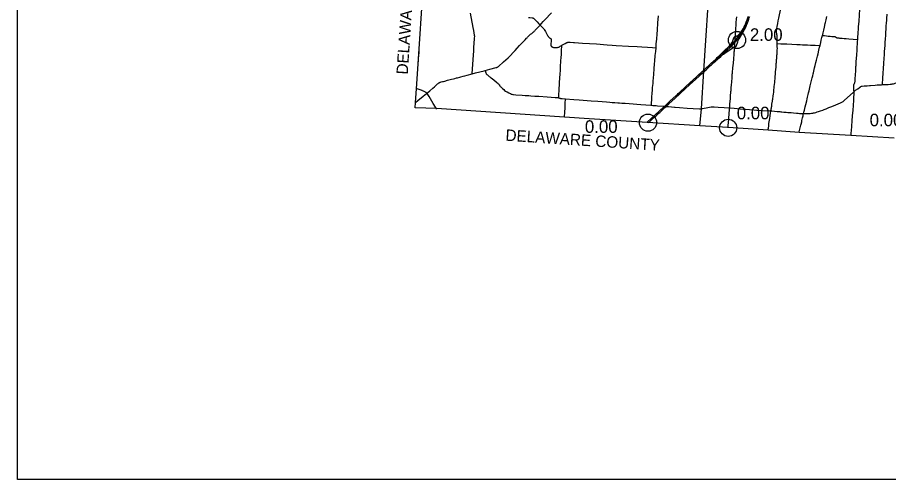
# Model space of a CAD drawing. Extents: x 1813937 to 1948437, y 826606 to 1022856.
# Drawn here: x 1813937 to 1890191, y 826606 to 867056 of the extents above; entities that cross this region are included whole.
import ezdxf

# ---------------------------------------------------------------- set-up
doc = ezdxf.new("R2010")
doc.units = 0
for name, color, linetype in [('Default', 7, 'Continuous'), ('GM_X_Adjacent_County_Text', 7, 'Continuous'), ('GM_X_County', 7, 'Continuous'), ('GM_X_County_Road', 7, 'Continuous'), ('GM_X_Interchange_Ramps', 7, 'Continuous'), ('GM_X_Interstate_Route', 7, 'Continuous'), ('GM_X_State_Route', 7, 'Continuous'), ('GM_X_Township', 7, 'Continuous'), ('GM_X_Township_Road', 7, 'Continuous'), ('SC_Scratch1', 7, 'Continuous')]:
    doc.layers.add(name, color=color, linetype=linetype)

msp = doc.modelspace()

# ---------------------------------------------------------------- linework, layer by layer
at = {"layer": 'Default'}
for centre in [(1876923, 865078), (1869130, 857850), (1876155, 857392)]:
    msp.add_circle(centre, 750, dxfattribs=at)
at = {"layer": 'GM_X_County'}
msp.add_lwpolyline([(1890695, 856480), (1886895, 856734), (1882352, 856998), (1879641, 857188), (1876143, 857428), (1873671, 857558), (1869100, 857855), (1863977, 858188), (1861827, 858324), (1850615, 859080), (1848752, 859146), (1848787, 859601), (1848864, 860810), (1849106, 864311), (1849634, 872258)], dxfattribs=at)
at = {"layer": 'GM_X_County_Road'}
for points in [[(1880446, 864770), (1880445, 864839), (1880441, 865118), (1880441, 865256), (1880436, 865364), (1880425, 865461), (1880415, 865553), (1880404, 865637), (1880388, 865760), (1880378, 865837), (1880375, 865898), (1880378, 865959), (1880388, 866024), (1880401, 866097), (1880436, 866266), (1880487, 866526), (1880531, 866751), (1880580, 866992), (1880753, 867844)], [(1853748, 862117), (1853750, 862165), (1853770, 862493), (1853801, 862984), (1853822, 863312), (1853856, 863803), (1853874, 864081), (1853894, 864409), (1853921, 864802), (1853950, 865195), (1853955, 865274), (1853961, 865391), (1853961, 865426), (1853960, 865457), (1853958, 865482), (1853954, 865506), (1853881, 865910), (1853831, 866184), (1853607, 867428)], [(1859687, 866387), (1859824, 866534), (1859968, 866692), (1860116, 866845), (1860675, 867445)], [(1869835, 864397), (1869843, 864490), (1869862, 864735), (1869893, 865144), (1869930, 865619), (1869952, 865930), (1870002, 866568), (1870050, 867206)], [(1884401, 865479), (1884424, 865573), (1884458, 865716), (1884513, 865939), (1884579, 866210), (1884651, 866513), (1884679, 866621), (1884706, 866733), (1884733, 866844), (1884766, 866988), (1884800, 867132)], [(1887494, 865122), (1887497, 865170), (1887500, 865235), (1887511, 865399), (1887526, 865595), (1887533, 865708), (1887559, 866050), (1887573, 866263), (1887603, 866704), (1887641, 867277), (1887670, 867741)], [(1854870, 862411), (1855302, 862523), (1855842, 862663), (1855880, 862674), (1855903, 862682), (1855921, 862689), (1855948, 862702), (1855990, 862727), (1856042, 862766), (1856484, 863158), (1856890, 863515), (1856986, 863605), (1857032, 863653), (1857075, 863700), (1857361, 864017), (1857505, 864175), (1857669, 864358), (1857895, 864595), (1858054, 864761), (1858190, 864904), (1858262, 864979), (1858381, 865102), (1858508, 865235), (1858543, 865271), (1858599, 865329), (1858715, 865445), (1858861, 865577), (1858960, 865663), (1859073, 865757), (1859126, 865803), (1859182, 865855), (1859217, 865889), (1859254, 865927), (1859342, 866020), (1859567, 866259), (1859687, 866387)], [(1859687, 866387), (1859699, 866375), (1859714, 866360), (1859801, 866272), (1859881, 866197), (1859909, 866170), (1859925, 866154), (1859941, 866138), (1859949, 866128), (1859963, 866112), (1859984, 866085), (1860010, 866049), (1860049, 865995), (1860149, 865825), (1860221, 865697), (1860311, 865522), (1860337, 865477), (1860361, 865438), (1860380, 865408), (1860397, 865384), (1860414, 865363), (1860432, 865343), (1860449, 865327), (1860477, 865302), (1860502, 865281), (1860538, 865255), (1860568, 865234), (1860596, 865215), (1860609, 865206), (1860618, 865199), (1860621, 865197), (1860624, 865194), (1860626, 865192), (1860629, 865189), (1860635, 865184), (1860643, 865175), (1860645, 865172), (1860648, 865168), (1860650, 865165), (1860652, 865162), (1860654, 865157), (1860655, 865154), (1860655, 865151), (1860656, 865149), (1860656, 865146), (1860656, 865113), (1860655, 865093), (1860652, 865044), (1860644, 864918), (1860636, 864801), (1860631, 864730), (1860628, 864661), (1860628, 864646), (1860628, 864634), (1860629, 864625), (1860630, 864613), (1860632, 864604), (1860634, 864595), (1860639, 864580), (1860643, 864573), (1860649, 864562), (1860656, 864553), (1860665, 864539), (1860676, 864528), (1860687, 864516), (1860699, 864504), (1860711, 864494), (1860718, 864488), (1860726, 864482), (1860736, 864475), (1860748, 864468), (1860761, 864462), (1860772, 864457), (1860784, 864451), (1860794, 864447), (1860805, 864443), (1860816, 864440), (1860856, 864428), (1860878, 864423), (1860920, 864417), (1860985, 864412), (1861066, 864413), (1861147, 864419), (1861212, 864429), (1861260, 864440), (1861322, 864462), (1861381, 864489), (1861452, 864528), (1861493, 864555), (1861570, 864613), (1861586, 864625), (1861605, 864638)], [(1861605, 864638), (1861697, 864680), (1861770, 864715), (1861870, 864769), (1862028, 864852), (1862073, 864871), (1862095, 864878), (1862120, 864885), (1862130, 864888), (1862150, 864891), (1862162, 864892), (1862171, 864892), (1862183, 864892), (1862201, 864892), (1862224, 864891), (1862257, 864889), (1862318, 864885), (1862619, 864866), (1862686, 864861), (1863397, 864814), (1864619, 864733), (1864959, 864711), (1865239, 864692), (1865546, 864671), (1866005, 864637), (1866352, 864612), (1867418, 864549), (1868175, 864502), (1868595, 864476), (1869081, 864445), (1869537, 864416), (1869835, 864397)], [(1880367, 863051), (1880377, 863199), (1880383, 863268), (1880391, 863382), (1880397, 863469), (1880406, 863567), (1880414, 863666), (1880419, 863752), (1880426, 863840), (1880432, 863919), (1880440, 864028), (1880446, 864115), (1880453, 864206), (1880455, 864322), (1880453, 864484), (1880446, 864770)], [(1884190, 864602), (1884252, 864855), (1884305, 865078), (1884359, 865302), (1884382, 865397), (1884401, 865479)], [(1887166, 860572), (1887164, 860625), (1887155, 860789), (1887150, 860871), (1887144, 860969), (1887141, 861068), (1887142, 861101), (1887145, 861134), (1887149, 861150), (1887153, 861166), (1887159, 861182), (1887173, 861212), (1887206, 861269), (1887221, 861298), (1887233, 861328), (1887242, 861359), (1887248, 861390), (1887254, 861455), (1887262, 861586), (1887268, 861701), (1887286, 861995), (1887312, 862404), (1887327, 862634), (1887335, 862748), (1887342, 862862), (1887349, 862961), (1887366, 863206), (1887382, 863451), (1887404, 863779), (1887432, 864188), (1887452, 864482), (1887469, 864728), (1887483, 864957), (1887494, 865122)], [(1861321, 860011), (1861325, 860133), (1861334, 860346), (1861349, 860624), (1861394, 861360), (1861419, 861736), (1861443, 862112), (1861461, 862407), (1861483, 862734), (1861517, 863257), (1861535, 863535), (1861551, 863797), (1861571, 864108), (1861605, 864638)], [(1869425, 859366), (1869437, 859552), (1869463, 859879), (1869479, 860092), (1869503, 860386), (1869527, 860714), (1869541, 860910), (1869571, 861286), (1869588, 861515), (1869606, 861727), (1869637, 862103), (1869675, 862561), (1869711, 862986), (1869732, 863231), (1869775, 863722), (1869807, 864081), (1869835, 864397)], [(1882749, 858641), (1882781, 858766), (1882823, 858927), (1882904, 859244), (1882948, 859428), (1883026, 859753), (1883068, 859929), (1883106, 860089), (1883158, 860312), (1883190, 860461), (1883229, 860629), (1883269, 860791), (1883333, 861063), (1883508, 861779), (1883548, 861938), (1883592, 862113), (1883612, 862192), (1883721, 862655), (1883766, 862846), (1883830, 863118), (1883877, 863309), (1883965, 863676), (1884016, 863883), (1884089, 864186), (1884150, 864441), (1884190, 864602)], [(1879893, 858874), (1879899, 858914), (1879910, 858992), (1879918, 859061), (1879931, 859139), (1879943, 859213), (1879959, 859293), (1879975, 859388), (1879986, 859464), (1880023, 859712), (1880035, 859806), (1880053, 859910), (1880067, 859997), (1880081, 860098), (1880092, 860193), (1880111, 860342), (1880134, 860505), (1880161, 860729), (1880175, 860889), (1880189, 861041), (1880201, 861164), (1880228, 861384), (1880242, 861531), (1880253, 861663), (1880270, 861893), (1880286, 862093), (1880305, 862302), (1880320, 862485), (1880339, 862702), (1880350, 862834), (1880360, 862959), (1880366, 863040), (1880367, 863051)], [(1849777, 860431), (1849850, 860491), (1850041, 860645), (1850308, 860862), (1850446, 860977), (1850478, 861005), (1850507, 861033), (1850563, 861092), (1850653, 861188), (1850701, 861232), (1850764, 861283), (1850793, 861303), (1850831, 861328), (1850859, 861344), (1850888, 861360), (1850911, 861370), (1850947, 861385), (1850983, 861397), (1851025, 861410), (1851135, 861438), (1851230, 861461), (1851339, 861488), (1851596, 861554), (1851929, 861642), (1852119, 861692), (1852230, 861721), (1852373, 861757), (1852468, 861781), (1852658, 861831), (1852753, 861857), (1852943, 861907), (1853101, 861949), (1853307, 862004), (1853748, 862117)], [(1853748, 862117), (1854032, 862192), (1854794, 862391), (1854870, 862411)], [(1854870, 862411), (1854930, 862215), (1854953, 862153), (1854969, 862124), (1854990, 862097), (1855014, 862074), (1855078, 862023), (1855155, 861962), (1855244, 861890), (1855295, 861849), (1855346, 861809), (1855409, 861760), (1855512, 861679), (1855626, 861586), (1855869, 861391), (1856010, 861278), (1856058, 861234), (1856088, 861197), (1856114, 861156), (1856165, 861072), (1856203, 861019), (1856248, 860970), (1856391, 860834), (1856500, 860735), (1856576, 860672), (1856656, 860616), (1856726, 860573), (1856799, 860535), (1856962, 860461), (1857066, 860408)], [(1887166, 860572), (1887216, 860614), (1887308, 860683), (1887494, 860818), (1887640, 860924), (1887720, 860982), (1887748, 861000), (1887777, 861016), (1887808, 861028), (1887824, 861033), (1887840, 861037), (1887873, 861041), (1888069, 861059), (1888315, 861078), (1888511, 861093), (1888609, 861101), (1889018, 861133), (1889182, 861145), (1889378, 861158), (1889558, 861167), (1889657, 861171)], [(1889657, 861171), (1889692, 861173), (1889953, 861185), (1890166, 861196), (1890328, 861205), (1890402, 861211), (1890451, 861216), (1890507, 861229), (1890555, 861240), (1890618, 861258), (1890993, 861378), (1891033, 861391)], [(1848788, 859619), (1848989, 859783), (1849459, 860167), (1849749, 860407), (1849777, 860431)], [(1849777, 860431), (1849754, 860451), (1849720, 860474), (1849689, 860493), (1849656, 860510), (1849607, 860535), (1849471, 860606), (1849401, 860638), (1849367, 860654), (1849322, 860671), (1849275, 860689), (1848916, 860807), (1848869, 860822)], [(1850650, 859027), (1850535, 859215), (1850337, 859536), (1850215, 859731), (1849965, 860136), (1849853, 860312), (1849793, 860405), (1849777, 860431)], [(1857066, 860408), (1857107, 860387), (1857180, 860350), (1857227, 860333), (1857291, 860318), (1857373, 860306), (1857569, 860289), (1858109, 860249), (1858370, 860230), (1858486, 860226), (1858568, 860230), (1858649, 860232), (1858698, 860229), (1858876, 860203), (1859220, 860178), (1859580, 860155), (1860300, 860108), (1861020, 860059), (1861051, 860056)], [(1882749, 858641), (1882876, 858641), (1883037, 858646), (1883179, 858653), (1883316, 858659), (1883436, 858668), (1883501, 858674), (1883566, 858683), (1883630, 858695), (1883710, 858714), (1883820, 858744), (1883946, 858781), (1884055, 858817), (1884240, 858883), (1884425, 858950), (1884563, 859003), (1884731, 859068), (1884976, 859162), (1885236, 859265), (1885584, 859409), (1885793, 859503), (1885987, 859592), (1886107, 859652), (1886158, 859681), (1886205, 859710), (1886235, 859732), (1886284, 859770), (1886345, 859827), (1887081, 860494), (1887166, 860572)], [(1886918, 856737), (1886925, 856900), (1886968, 857475), (1887012, 858072), (1887069, 858727), (1887080, 858891), (1887115, 859398), (1887142, 859758), (1887156, 859987), (1887164, 860134), (1887171, 860293), (1887170, 860478), (1887166, 860572)], [(1861051, 860056), (1861090, 860053), (1861142, 860048), (1861186, 860042), (1861231, 860034), (1861310, 860014), (1861321, 860011)], [(1861321, 860011), (1861372, 859994), (1861409, 859984), (1861436, 859978), (1861469, 859971), (1861517, 859963), (1861564, 859957), (1861615, 859951), (1861909, 859928), (1861916, 859928)], [(1861835, 858314), (1861835, 858351), (1861835, 858433), (1861846, 858662), (1861854, 858810), (1861870, 859072), (1861880, 859252), (1861895, 859531), (1861916, 859928)], [(1861916, 859928), (1862629, 859873), (1863120, 859837), (1864150, 859761), (1864739, 859716), (1865507, 859658), (1865802, 859636), (1865998, 859622), (1866227, 859604), (1866505, 859582), (1866652, 859574), (1866832, 859561), (1867127, 859537), (1867486, 859512), (1868517, 859434), (1869367, 859370), (1869425, 859366)], [(1869425, 859366), (1869563, 859355), (1869793, 859339), (1869857, 859334)], [(1869857, 859334), (1869972, 859325), (1870512, 859285), (1870571, 859280), (1870708, 859269), (1870720, 859268), (1870937, 859253), (1871199, 859232), (1871452, 859211)], [(1871452, 859211), (1871509, 859207), (1871885, 859178), (1872572, 859126), (1873096, 859088), (1873652, 859052), (1873735, 859052), (1873770, 859055)], [(1873770, 859055), (1873817, 859059), (1873914, 859075), (1874364, 859169), (1874653, 859228), (1874683, 859233), (1874719, 859239), (1874747, 859242), (1874759, 859243), (1874778, 859244), (1874831, 859245), (1874929, 859242), (1875273, 859215), (1875796, 859173), (1876256, 859137), (1876281, 859135)], [(1876281, 859135), (1876663, 859106), (1877195, 859066), (1877490, 859039), (1877653, 859024), (1878012, 858994), (1878385, 858961), (1878670, 858941), (1879005, 858919), (1879153, 858913), (1879766, 858880), (1879893, 858874)], [(1879641, 857189), (1879648, 857220), (1879655, 857263), (1879670, 857355), (1879696, 857575), (1879722, 857780), (1879765, 858069), (1879788, 858222), (1879825, 858438), (1879867, 858697), (1879885, 858819), (1879893, 858874)], [(1879893, 858874), (1879982, 858869), (1880208, 858853), (1880429, 858833), (1880554, 858821), (1880668, 858808), (1880755, 858798), (1880836, 858790), (1881016, 858774), (1881229, 858754), (1881359, 858743), (1881425, 858738), (1881490, 858733), (1881654, 858720), (1881866, 858702), (1882144, 858679), (1882275, 858668), (1882389, 858660), (1882552, 858648), (1882650, 858642), (1882716, 858641), (1882749, 858641)], [(1882360, 857020), (1882365, 857041), (1882508, 857614), (1882537, 857726), (1882584, 857918), (1882612, 858029), (1882663, 858259), (1882703, 858442), (1882727, 858546), (1882745, 858623), (1882749, 858641)]]:
    msp.add_lwpolyline(points, dxfattribs=at)
at = {"layer": 'GM_X_Interchange_Ramps'}
for points in [[(1876717, 864449), (1876728, 864453), (1876744, 864458), (1876759, 864464), (1876774, 864472), (1876787, 864481), (1876801, 864491), (1876813, 864502), (1876835, 864526), (1876855, 864553), (1876871, 864581), (1876884, 864612), (1876988, 864907), (1877035, 865030), (1877067, 865106), (1877097, 865165), (1877129, 865223), (1877190, 865321), (1877330, 865544), (1877420, 865696), (1877535, 865901), (1877630, 866090), (1877723, 866300)], [(1877739, 866630), (1877658, 866474), (1877610, 866370), (1877566, 866282), (1877511, 866181), (1877454, 866082), (1877393, 865984), (1877321, 865875), (1877256, 865781), (1877197, 865702), (1877136, 865625), (1877083, 865562), (1877039, 865513), (1877005, 865478), (1876980, 865456), (1876954, 865437), (1876926, 865420), (1876911, 865413), (1876896, 865407), (1876880, 865402), (1876864, 865399), (1876846, 865396), (1876780, 865386)], [(1876780, 865386), (1876771, 865384), (1876755, 865381), (1876740, 865375), (1876725, 865368), (1876711, 865360), (1876698, 865350), (1876686, 865339), (1876675, 865327), (1876655, 865301), (1876639, 865273), (1876617, 865228), (1876551, 865061), (1876520, 864985), (1876494, 864925), (1876458, 864852), (1876426, 864795), (1876391, 864740), (1876353, 864686), (1876313, 864635), (1876269, 864586), (1876201, 864516), (1875824, 864151), (1875544, 863864)], [(1874882, 863099), (1875062, 863245), (1875136, 863311), (1875184, 863355), (1875233, 863400), (1875341, 863501), (1875498, 863646), (1875597, 863734), (1875673, 863797), (1875738, 863847), (1875818, 863905), (1875981, 864016), (1876376, 864285), (1876511, 864379), (1876552, 864406), (1876581, 864422), (1876595, 864429), (1876611, 864435), (1876631, 864439), (1876656, 864442), (1876684, 864445), (1876717, 864449)]]:
    msp.add_lwpolyline(points, dxfattribs=at)
at = {"layer": 'GM_X_Interstate_Route'}
for points in [[(1869023, 857856), (1869132, 857953), (1869385, 858187), (1869772, 858542), (1869844, 858608), (1870048, 858799), (1870193, 858932), (1870265, 858999), (1870374, 859099), (1870507, 859221), (1870571, 859280), (1870628, 859332), (1870772, 859465), (1870881, 859564), (1870942, 859620), (1871014, 859687), (1871074, 859743), (1871339, 859988), (1871604, 860232), (1871701, 860322), (1871772, 860389), (1871906, 860510), (1872087, 860677), (1872231, 860811), (1872304, 860877), (1872509, 861066), (1872593, 861145), (1872641, 861189), (1872787, 861322), (1872859, 861388), (1873052, 861567), (1873136, 861644), (1873196, 861700), (1873280, 861778), (1873341, 861833), (1873474, 861955), (1873546, 862023), (1873776, 862233), (1873872, 862322), (1873983, 862423), (1874126, 862554), (1874247, 862666), (1874415, 862822), (1874620, 863011), (1874704, 863089), (1874801, 863178), (1875115, 863466), (1875200, 863544), (1875368, 863700), (1875544, 863864), (1875913, 864199), (1876410, 864663), (1876625, 864894), (1876757, 865045), (1876783, 865075), (1876966, 865303), (1877113, 865499), (1877223, 865663), (1877384, 865923), (1877464, 866066), (1877549, 866221), (1877631, 866391), (1877739, 866630), (1877827, 866853), (1877884, 867020), (1877926, 867161)], [(1876975, 865128), (1877043, 865211), (1877201, 865430), (1877316, 865592), (1877499, 865892), (1877609, 866089), (1877723, 866300), (1877753, 866369), (1877785, 866444), (1877841, 866581), (1877894, 866719), (1877928, 866811), (1877961, 866904), (1878001, 867028), (1878035, 867138)], [(1876614, 864715), (1876616, 864717), (1876744, 864855), (1876819, 864937), (1876975, 865128)], [(1870992, 859518), (1871483, 859969), (1871941, 860392), (1872388, 860803), (1872774, 861159), (1873317, 861659), (1873920, 862215), (1873973, 862265), (1874210, 862482), (1874608, 862849), (1874681, 862916), (1874741, 862971), (1874826, 863048), (1874882, 863099), (1875427, 863601), (1876330, 864435), (1876614, 864715)], [(1870487, 859053), (1870493, 859058), (1870601, 859158), (1870720, 859268), (1870794, 859336), (1870963, 859492), (1870992, 859518)], [(1869179, 857847), (1869251, 857912), (1869624, 858258), (1869805, 858424), (1870070, 858669), (1870155, 858747), (1870360, 858936), (1870432, 859003), (1870487, 859053)]]:
    msp.add_lwpolyline(points, dxfattribs=at)
at = {"layer": 'GM_X_State_Route'}
for points in [[(1876826, 866049), (1876829, 866090), (1876849, 866385), (1876865, 866614), (1876887, 866908), (1876904, 867104)], [(1876679, 863895), (1876685, 863983), (1876689, 864037), (1876696, 864130), (1876715, 864422), (1876717, 864449), (1876730, 864651), (1876743, 864847), (1876744, 864855), (1876757, 865045), (1876765, 865174), (1876780, 865386), (1876781, 865403), (1876801, 865698), (1876813, 865878), (1876826, 866049)], [(1876144, 857406), (1876149, 857465), (1876155, 857548), (1876187, 857916), (1876203, 858112), (1876220, 858341), (1876232, 858488), (1876251, 858733), (1876261, 858881), (1876279, 859106), (1876281, 859135), (1876289, 859220), (1876297, 859335), (1876310, 859481), (1876347, 859935), (1876356, 860066), (1876368, 860212), (1876387, 860474), (1876395, 860572), (1876402, 860653), (1876412, 860784), (1876426, 860964), (1876436, 861095), (1876465, 861454), (1876487, 861748), (1876503, 861944), (1876514, 862080), (1876521, 862188), (1876530, 862287), (1876538, 862385), (1876549, 862499), (1876563, 862630), (1876586, 862841), (1876607, 863054), (1876620, 863170), (1876635, 863308), (1876643, 863426), (1876656, 863559), (1876667, 863721), (1876679, 863895)]]:
    msp.add_lwpolyline(points, dxfattribs=at)
at = {"layer": 'GM_X_Township'}
msp.add_lwpolyline([(1873671, 857558), (1873806, 859043), (1874029, 862389), (1874586, 870801), (1874844, 874776), (1875147, 880018), (1875287, 882532), (1875268, 882593), (1875339, 883824), (1877996, 883681), (1878453, 883649), (1879771, 883544), (1879947, 883530), (1880714, 883463), (1881064, 883424), (1881619, 883383), (1882389, 883337), (1886519, 883080), (1888679, 882953), (1894036, 882664)], dxfattribs=at)
at = {"layer": 'GM_X_Township_Road'}
for points in [[(1858684, 867058), (1858690, 867054), (1858697, 867050), (1858704, 867048), (1858711, 867045), (1858719, 867043), (1858728, 867041), (1858733, 867040), (1858739, 867039), (1858753, 867038), (1858792, 867035), (1858989, 867023), (1859020, 867020), (1859040, 867018), (1859050, 867017), (1859064, 867014), (1859071, 867012), (1859077, 867009), (1859088, 867004), (1859097, 866998), (1859105, 866992), (1859115, 866985), (1859122, 866978), (1859162, 866939), (1859419, 866664), (1859579, 866501), (1859687, 866387)], [(1889657, 861171), (1889658, 861209), (1889660, 861291), (1889668, 861415), (1889676, 861537), (1889682, 861643), (1889693, 861798), (1889697, 861864), (1889707, 862060), (1889720, 862257), (1889736, 862486), (1889749, 862666), (1889769, 862928), (1889784, 863158), (1889797, 863338), (1889814, 863567), (1889821, 863682), (1889835, 863911), (1889849, 864108), (1889863, 864321), (1889885, 864632), (1889901, 864894), (1889919, 865156), (1889941, 865500), (1889952, 865681), (1889961, 865828), (1889972, 865975), (1889992, 866320), (1890007, 866549), (1890026, 866828), (1890035, 866959), (1890060, 867352)], [(1880446, 864770), (1880459, 864770), (1880770, 864758), (1880963, 864750), (1881280, 864737), (1882157, 864696), (1882446, 864678), (1882658, 864663), (1882787, 864656), (1882927, 864653), (1883100, 864647), (1883361, 864637), (1883772, 864617), (1884167, 864603), (1884190, 864602)], [(1884401, 865479), (1884430, 865476), (1884528, 865465), (1884577, 865461), (1884757, 865442), (1884904, 865429), (1885084, 865411), (1885231, 865396), (1885345, 865386), (1885443, 865381), (1885476, 865377), (1885492, 865373), (1885507, 865368), (1885522, 865362), (1885551, 865346), (1885607, 865312), (1885636, 865296), (1885666, 865284), (1885698, 865275), (1885730, 865268), (1885762, 865262), (1885827, 865256), (1885909, 865251), (1885975, 865249), (1886122, 865238), (1886302, 865224), (1886482, 865208), (1886711, 865189), (1887464, 865124), (1887494, 865122)], [(1849021, 862856), (1849057, 863463), (1849090, 863978), (1849102, 864092), (1849117, 864321), (1849117, 864329), (1849117, 864338), (1849117, 864343), (1849117, 864351), (1849116, 864355), (1849116, 864358), (1849115, 864361), (1849113, 864368), (1849111, 864373), (1849108, 864379)]]:
    msp.add_lwpolyline(points, dxfattribs=at)
at = {"layer": 'SC_Scratch1'}
msp.add_lwpolyline([(1813937, 826606), (1813937, 1022856), (1948437, 1022856), (1948437, 826606)], close=True, dxfattribs=at)

# ---------------------------------------------------------------- texts
at = {"layer": 'Default'}
for s, p in [('2.00', (1878053, 865004)), ('0.00', (1876905, 858142)), ('0.00', (1888535, 857530)), ('0.00', (1863610, 856952))]:
    msp.add_text(s, height=1100, dxfattribs=at).set_placement(p)
at = {"layer": 'GM_X_Adjacent_County_Text'}
for rotation, p in [(86.22308, (1848101, 862036)), (356.22308, (1856635, 856270))]:
    msp.add_text('DELAWARE COUNTY', height=1000, rotation=rotation, dxfattribs=at).set_placement(p)

doc.saveas('drawing.dxf')
